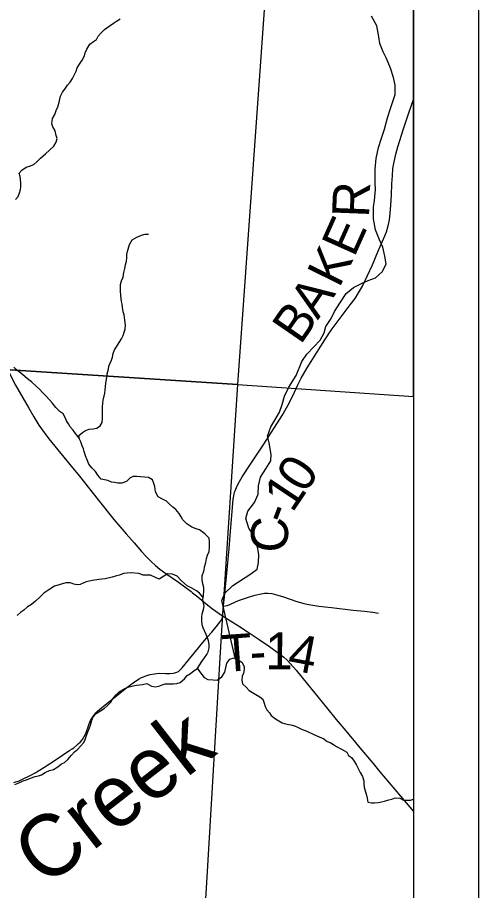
# Model space of a CAD drawing. Extents: x -8.2 to 34, y 0 to 22.
# Drawn here: x 8.292 to 9, y 18.744 to 20.084 of the extents above; entities that cross this region are included whole.
import ezdxf

# ---------------------------------------------------------------- set-up
doc = ezdxf.new("R2010")
doc.units = 0
for name, color, linetype in [('GM_X_Corporation', 7, 'Continuous'), ('GM_X_County_Road', 7, 'Continuous'), ('GM_X_County_Road_Text', 7, 'Continuous'), ('GM_X_Minor_River', 7, 'Continuous'), ('GM_X_Minor_River_Text', 7, 'Continuous'), ('GM_X_State_Route', 7, 'Continuous'), ('GM_X_Township_Road', 7, 'Continuous'), ('GM_X_Township_Road_Text', 7, 'Continuous'), ('SH_Data', 7, 'Continuous')]:
    doc.layers.add(name, color=color, linetype=linetype)

msp = doc.modelspace()

# ---------------------------------------------------------------- linework, layer by layer
at = {"layer": 'GM_X_Corporation'}
for points in [[(7.6877, 20.6096), (8.7029, 20.5419), (8.6299, 19.5206), (7.6147, 19.5864)], [(8.9, 19.5025), (8.9, 20.5285), (8.7029, 20.5419), (8.6299, 19.5206)], [(7.6147, 19.5864), (8.6299, 19.5206), (8.6049, 19.1351), (8.5816, 18.7383), (8.5636, 18.5025), (7.9912, 18.537), (7.548, 18.5656), (7.5613, 18.7777), (7.5889, 19.1864)]]:
    msp.add_lwpolyline(points, close=True, dxfattribs=at)
at = {"layer": 'GM_X_County_Road'}
for points in [[(8.6077, 19.1703), (8.6086, 19.1801), (8.6087, 19.1813), (8.61, 19.1947), (8.6135, 19.231), (8.617, 19.269), (8.619, 19.2886), (8.6214, 19.3195), (8.6222, 19.3317), (8.6235, 19.3444), (8.6248, 19.3524), (8.6256, 19.3556), (8.6263, 19.3574), (8.6285, 19.3627), (8.6309, 19.3679), (8.6371, 19.3789), (8.649, 19.3969), (8.6704, 19.429), (8.6984, 19.4731), (8.7094, 19.492), (8.7176, 19.5089), (8.7227, 19.5202), (8.7277, 19.5302), (8.737, 19.5463), (8.7518, 19.5697), (8.7641, 19.5894), (8.7736, 19.604), (8.7874, 19.6228), (8.8032, 19.6428), (8.8105, 19.6529), (8.8159, 19.6613), (8.8217, 19.6717), (8.8297, 19.6879), (8.8371, 19.7044), (8.8455, 19.7244), (8.8561, 19.7489), (8.8585, 19.7554), (8.8611, 19.7644), (8.8631, 19.7736), (8.8646, 19.7835), (8.8656, 19.7959), (8.8663, 19.8114), (8.8669, 19.8287), (8.8677, 19.841), (8.8687, 19.8522), (8.8705, 19.8627), (8.8732, 19.8746), (8.8763, 19.8859), (8.885, 19.9131), (8.8922, 19.9349), (8.8971, 19.9496), (8.9, 19.9584)], [(8.2869, 18.9093), (8.2948, 18.9123), (8.2992, 18.9141), (8.3031, 18.916), (8.3066, 18.9178), (8.3116, 18.9203), (8.3195, 18.9246), (8.3326, 18.9327), (8.35, 18.9439), (8.3729, 18.959), (8.3762, 18.9612), (8.3786, 18.9629), (8.3833, 18.9667), (8.3857, 18.9688), (8.3889, 18.9719), (8.392, 18.9757), (8.3948, 18.9801), (8.3966, 18.9838), (8.3982, 18.988), (8.4006, 18.9948), (8.4023, 18.9994), (8.4046, 19.0046), (8.4063, 19.0077), (8.4082, 19.0106), (8.4128, 19.0166), (8.4153, 19.0192), (8.418, 19.0217), (8.4268, 19.0288), (8.4622, 19.0569), (8.472, 19.0643), (8.4791, 19.0688), (8.4828, 19.0708), (8.4855, 19.072), (8.4909, 19.074), (8.4959, 19.0752), (8.5024, 19.0764), (8.506, 19.0768), (8.5103, 19.0772), (8.5196, 19.0769), (8.5264, 19.0767), (8.5312, 19.0773), (8.534, 19.0779), (8.5368, 19.079), (8.5393, 19.0802), (8.5418, 19.0824), (8.545, 19.0856), (8.5566, 19.0995), (8.5634, 19.1079), (8.5722, 19.1187), (8.5843, 19.1336), (8.5906, 19.1406), (8.5992, 19.1509), (8.6043, 19.158), (8.606, 19.1608), (8.6068, 19.1631), (8.6071, 19.1657)], [(8.6071, 19.1657), (8.6076, 19.1694), (8.6077, 19.1703)]]:
    msp.add_lwpolyline(points, dxfattribs=at)
at = {"layer": 'GM_X_Minor_River'}
for points in [[(8.6272, 19.0985), (8.606, 19.1888), (8.6108, 19.2005), (8.6227, 19.2121), (8.6503, 19.2299), (8.6603, 19.2373), (8.6623, 19.2476), (8.6629, 19.2593), (8.6611, 19.2689), (8.6565, 19.286), (8.6476, 19.3003), (8.6429, 19.3148), (8.6461, 19.3261), (8.6562, 19.3393), (8.6617, 19.3521), (8.6623, 19.365), (8.6651, 19.3783), (8.6733, 19.3914), (8.6811, 19.4035), (8.6816, 19.413), (8.6785, 19.4312), (8.6763, 19.4412), (8.6811, 19.4559), (8.6874, 19.4661), (8.6944, 19.4781), (8.6987, 19.4898), (8.7023, 19.5027), (8.7086, 19.5166), (8.7199, 19.5347), (8.729, 19.5562), (8.7363, 19.5671), (8.7471, 19.5784), (8.7568, 19.5888), (8.763, 19.5998), (8.7658, 19.6096), (8.774, 19.622), (8.7791, 19.6329), (8.7873, 19.6457), (8.7966, 19.6604), (8.8081, 19.6697), (8.8203, 19.6756), (8.8307, 19.6804), (8.8421, 19.6844), (8.8525, 19.6941), (8.8584, 19.7061), (8.8563, 19.718), (8.8531, 19.7317), (8.8479, 19.7428), (8.8417, 19.7581), (8.839, 19.7749), (8.8389, 19.7931), (8.8402, 19.8034), (8.8416, 19.8201), (8.8413, 19.8299), (8.8411, 19.8417), (8.8413, 19.8516), (8.8431, 19.8679), (8.8464, 19.8846), (8.8511, 19.8989), (8.8559, 19.9129), (8.8604, 19.9303), (8.8647, 19.9443), (8.8687, 19.9553), (8.8719, 19.9659), (8.8721, 19.9803), (8.8697, 19.9921), (8.865, 20.0066), (8.8587, 20.0212), (8.8536, 20.0315), (8.8485, 20.0445), (8.8471, 20.0544), (8.844, 20.0716), (8.8355, 20.0862)], [(8.2891, 19.805), (8.2936, 19.8092), (8.2955, 19.8149), (8.2969, 19.8199), (8.2973, 19.8244), (8.2976, 19.8298), (8.2971, 19.8355), (8.2963, 19.84), (8.2951, 19.8453), (8.2989, 19.8499), (8.3057, 19.8542), (8.3106, 19.8561), (8.3174, 19.8584), (8.3223, 19.8631), (8.3275, 19.8684), (8.3354, 19.875), (8.3482, 19.8865), (8.3519, 19.8926), (8.353, 19.8983), (8.3518, 19.9032), (8.3502, 19.9104), (8.3464, 19.9165), (8.3452, 19.921), (8.3463, 19.929), (8.3496, 19.9355), (8.3518, 19.9416), (8.354, 19.9473), (8.3562, 19.9542), (8.3584, 19.9633), (8.3614, 19.9694), (8.3648, 19.9744), (8.3689, 19.9805), (8.373, 19.9851), (8.3767, 19.9905), (8.3793, 19.9955), (8.3823, 20.0019), (8.3841, 20.0069), (8.3886, 20.0142), (8.3916, 20.0188), (8.3953, 20.0253), (8.3961, 20.0298), (8.3986, 20.0359), (8.4035, 20.0432), (8.4091, 20.0474), (8.4137, 20.0505), (8.4159, 20.0555), (8.4208, 20.0608), (8.4257, 20.0658), (8.4328, 20.0712), (8.4396, 20.0758), (8.4445, 20.0785), (8.4501, 20.0824)], [(8.4381, 19.5628), (8.4392, 19.5681), (8.4414, 19.5738), (8.4444, 19.5784), (8.4482, 19.5853), (8.4519, 19.5907), (8.4545, 19.596), (8.4563, 19.601), (8.4574, 19.6055), (8.4581, 19.612), (8.4573, 19.6196), (8.4561, 19.6276), (8.4545, 19.6321), (8.4537, 19.6393), (8.4532, 19.6439), (8.452, 19.6484), (8.4512, 19.6575), (8.4504, 19.6644), (8.4503, 19.6693), (8.4506, 19.6743), (8.4521, 19.68), (8.4543, 19.6857), (8.4558, 19.6925), (8.4572, 19.6986), (8.4583, 19.7047), (8.4594, 19.7101), (8.4601, 19.7154), (8.4604, 19.7203), (8.4611, 19.7249), (8.4644, 19.7359), (8.4685, 19.7428), (8.4753, 19.7471), (8.4825, 19.7498), (8.4882, 19.7514), (8.4935, 19.7514)], [(8.5682, 19.0843), (8.5755, 19.0955), (8.5796, 19.1009), (8.583, 19.1059), (8.5852, 19.1104), (8.5863, 19.1165), (8.5866, 19.1215), (8.5854, 19.1272), (8.5842, 19.1317), (8.5819, 19.1366), (8.5792, 19.1423), (8.5772, 19.1468), (8.5757, 19.1518), (8.5752, 19.1582), (8.5755, 19.1636), (8.5759, 19.1685), (8.5777, 19.175), (8.5788, 19.1803), (8.578, 19.1849), (8.5768, 19.1902), (8.5779, 19.1966), (8.5782, 19.2039), (8.5781, 19.2088), (8.5765, 19.2164), (8.5757, 19.2213), (8.576, 19.227), (8.5782, 19.2339), (8.58, 19.2423), (8.5815, 19.2472), (8.5826, 19.2537), (8.584, 19.2586), (8.5863, 19.2644), (8.5873, 19.2716), (8.5872, 19.2788), (8.5864, 19.2849), (8.5799, 19.2913), (8.5719, 19.2973), (8.5665, 19.2991), (8.5601, 19.3017), (8.5524, 19.3066), (8.5463, 19.313), (8.5436, 19.3175), (8.5405, 19.3224), (8.5355, 19.3289), (8.5309, 19.3322), (8.5259, 19.3371), (8.5209, 19.3416), (8.5148, 19.3446), (8.5083, 19.3484), (8.5041, 19.3559), (8.5029, 19.3639), (8.5013, 19.37), (8.4997, 19.3745), (8.4936, 19.3779), (8.4871, 19.3786), (8.475, 19.3796), (8.47, 19.3795), (8.4651, 19.3776), (8.4599, 19.3719), (8.4527, 19.3691), (8.4462, 19.3694), (8.4413, 19.3702), (8.4367, 19.3709), (8.431, 19.3731), (8.4208, 19.3753), (8.4158, 19.3817), (8.4119, 19.387), (8.4065, 19.3926), (8.4019, 19.3983), (8.3992, 19.4051), (8.3965, 19.4112), (8.3945, 19.4176), (8.3937, 19.4221), (8.3918, 19.4267), (8.3894, 19.4324), (8.3875, 19.4369), (8.3863, 19.4422), (8.3919, 19.4468), (8.3968, 19.4499), (8.4025, 19.4523), (8.4086, 19.4527), (8.4139, 19.4535), (8.4191, 19.4574), (8.4221, 19.4623), (8.4228, 19.4688), (8.4227, 19.4809), (8.423, 19.487), (8.4233, 19.4916), (8.424, 19.4965), (8.4266, 19.5076), (8.4272, 19.5175), (8.4279, 19.5224), (8.4294, 19.5319), (8.4301, 19.5373), (8.4319, 19.5445), (8.4326, 19.5491), (8.4367, 19.5582), (8.4381, 19.5628)], [(8.3872, 19.4383), (8.3813, 19.4452), (8.3778, 19.4505), (8.3732, 19.4558), (8.3705, 19.4603), (8.3674, 19.4648), (8.3655, 19.4701), (8.3624, 19.4754), (8.3578, 19.4788), (8.3513, 19.4852), (8.3455, 19.4924), (8.3417, 19.4973), (8.3359, 19.5033), (8.3309, 19.5086), (8.3267, 19.5131), (8.3217, 19.5176), (8.3137, 19.5248), (8.3076, 19.5296), (8.2999, 19.536), (8.2926, 19.5417), (8.2865, 19.5473)], [(8.5771, 19.1938), (8.5717, 19.2), (8.5672, 19.2038), (8.5599, 19.2079), (8.553, 19.2116), (8.5481, 19.2154), (8.5435, 19.2199), (8.5373, 19.2263), (8.5305, 19.2293), (8.5232, 19.2299), (8.5168, 19.2265), (8.51, 19.2215), (8.5043, 19.2244), (8.4967, 19.2278), (8.4899, 19.2277), (8.4853, 19.2277), (8.4788, 19.2307), (8.4667, 19.2313), (8.4606, 19.2309), (8.4549, 19.2304), (8.4489, 19.2281), (8.4443, 19.2269), (8.4379, 19.225), (8.4269, 19.2222), (8.4216, 19.2218), (8.4171, 19.221), (8.4076, 19.2197), (8.4023, 19.2185), (8.3977, 19.2177), (8.3932, 19.2154), (8.3883, 19.2135), (8.3837, 19.213), (8.3788, 19.2141), (8.3738, 19.216), (8.3663, 19.2163), (8.3579, 19.2136), (8.3489, 19.2108), (8.3402, 19.2054), (8.333, 19.2004), (8.327, 19.1947), (8.3199, 19.1881), (8.3138, 19.1831), (8.3078, 19.1793), (8.3018, 19.1743), (8.2973, 19.1712), (8.292, 19.1662)], [(8.2883, 18.9062), (8.2936, 18.9086), (8.3008, 18.9121), (8.306, 18.9136), (8.3121, 18.916), (8.3193, 18.9187), (8.3246, 18.9199), (8.3291, 18.9214), (8.3348, 18.9249), (8.3416, 18.928), (8.3476, 18.9296), (8.354, 18.9335), (8.3601, 18.9381), (8.3646, 18.94), (8.3695, 18.945), (8.3751, 18.9515), (8.38, 18.9565), (8.3849, 18.9607), (8.3939, 18.9707), (8.3961, 18.9753), (8.3983, 18.9818), (8.4002, 18.9871), (8.4031, 18.9932), (8.4046, 18.9978), (8.4064, 19.005), (8.4086, 19.0104), (8.4131, 19.0157), (8.4196, 19.0196), (8.4256, 19.0231), (8.4301, 19.0273), (8.4354, 19.033), (8.438, 19.0376), (8.4436, 19.0441), (8.4485, 19.0487), (8.4534, 19.0518), (8.4579, 19.0545), (8.4636, 19.0565), (8.47, 19.0577), (8.4749, 19.0589), (8.4795, 19.0593), (8.4844, 19.0601), (8.4908, 19.0613), (8.4981, 19.0576), (8.5034, 19.0565), (8.5091, 19.0573), (8.5144, 19.0596), (8.5189, 19.0608), (8.5254, 19.0612), (8.5318, 19.0609), (8.5368, 19.0617), (8.5421, 19.0633), (8.5488, 19.0687), (8.5526, 19.074), (8.5579, 19.0767), (8.5635, 19.0817), (8.5684, 19.0844), (8.5715, 19.0799), (8.5753, 19.0754), (8.5788, 19.0705), (8.5845, 19.0679), (8.5929, 19.0672), (8.5986, 19.0669), (8.6061, 19.0719), (8.6106, 19.0788), (8.6128, 19.0883), (8.6139, 19.0928), (8.6183, 19.099), (8.6248, 19.1009), (8.6309, 19.098), (8.6366, 19.0942), (8.6401, 19.0878), (8.6405, 19.0828), (8.6394, 19.0775), (8.6372, 19.0729), (8.6365, 19.0665), (8.6377, 19.0612), (8.6431, 19.0559), (8.6477, 19.051), (8.653, 19.0476), (8.658, 19.0446), (8.6645, 19.0409), (8.6691, 19.0375), (8.6711, 19.0311), (8.6726, 19.0261), (8.675, 19.0212), (8.6792, 19.0167), (8.6819, 19.0122), (8.6884, 19.0073), (8.6933, 19.0043), (8.6987, 19.0013), (8.7059, 18.9991), (8.712, 18.998), (8.7177, 18.9965), (8.7223, 18.9947), (8.7284, 18.9913), (8.7364, 18.9884), (8.7471, 18.9831), (8.7555, 18.9798), (8.7623, 18.9764), (8.7677, 18.9727), (8.7723, 18.9708)], [(8.7723, 18.9708), (8.7772, 18.9678), (8.7818, 18.9648), (8.7898, 18.9607), (8.7978, 18.9559), (8.8002, 18.951), (8.8048, 18.948), (8.809, 18.9423), (8.8129, 18.9359), (8.8152, 18.931), (8.8183, 18.9249), (8.8221, 18.9185), (8.8237, 18.912), (8.8238, 18.9071), (8.8246, 18.9022), (8.8258, 18.8969), (8.8281, 18.89), (8.8293, 18.8855), (8.8301, 18.8794), (8.8359, 18.8783), (8.8404, 18.8784), (8.8457, 18.8788), (8.851, 18.88), (8.8556, 18.8808), (8.8624, 18.8828), (8.8669, 18.8839), (8.8722, 18.8859), (8.8794, 18.8852), (8.8848, 18.8826), (8.8897, 18.8823), (8.8958, 18.8823), (8.9, 18.8841)]]:
    msp.add_lwpolyline(points, dxfattribs=at)
at = {"layer": 'GM_X_State_Route'}
for points in [[(8.2752, 19.5469), (8.2893, 19.5198), (8.3007, 19.5002), (8.3098, 19.4841), (8.3173, 19.4708), (8.3249, 19.4585), (8.3332, 19.4468), (8.3405, 19.4375), (8.3589, 19.4148), (8.3726, 19.3981), (8.3877, 19.3798), (8.4162, 19.3436), (8.4404, 19.3134), (8.4591, 19.2914), (8.4714, 19.2774), (8.4828, 19.2643), (8.4903, 19.256), (8.4973, 19.2489), (8.5042, 19.2425), (8.5109, 19.2371), (8.5199, 19.2304), (8.5393, 19.2169), (8.5589, 19.2027), (8.5612, 19.2008)], [(8.5612, 19.2008), (8.569, 19.1946), (8.5819, 19.1839), (8.5918, 19.1762), (8.6071, 19.1657), (8.6318, 19.1499), (8.6448, 19.1414), (8.6633, 19.129), (8.6789, 19.1181), (8.693, 19.1082), (8.701, 19.102), (8.7056, 19.0979), (8.7116, 19.0918), (8.7201, 19.0819), (8.7373, 19.0607), (8.7467, 19.0491), (8.7667, 19.0245), (8.7817, 19.0063), (8.7964, 18.9886), (8.8055, 18.9776), (8.8091, 18.9733), (8.8154, 18.9657), (8.8265, 18.9523), (8.8381, 18.9385), (8.8483, 18.926), (8.8629, 18.909), (8.889, 18.8782), (8.9, 18.8652)]]:
    msp.add_lwpolyline(points, dxfattribs=at)
at = {"layer": 'GM_X_Township_Road'}
msp.add_lwpolyline([(8.6086, 19.1801), (8.6144, 19.1813), (8.6171, 19.1822), (8.6195, 19.1835), (8.6316, 19.1888), (8.6439, 19.1932), (8.6564, 19.197), (8.6661, 19.1993), (8.6716, 19.2001), (8.6766, 19.2002), (8.6827, 19.1995), (8.69, 19.1978), (8.6989, 19.1951), (8.7211, 19.1873), (8.7265, 19.1857), (8.732, 19.1843), (8.7393, 19.1829), (8.7547, 19.1804), (8.7741, 19.1782), (8.8076, 19.1742), (8.8251, 19.1725), (8.8377, 19.1711), (8.8463, 19.1697)], dxfattribs=at)
at = {"layer": 'SH_Data'}
for p, q in [((9, 21), (9, 14)), ((8.9, 20.9), (8.9, 14.1))]:
    msp.add_line(p, q, dxfattribs=at)

# ---------------------------------------------------------------- texts
at = {"layer": 'GM_X_County_Road_Text'}
for s, rotation, p in [('R', 87.7824, (8.8318, 19.7764)), ('E', 65.9004, (8.8091, 19.7147)), ('K', 63.7729, (8.786, 19.6678)), ('A', 55.585, (8.7533, 19.6189)), ('B', 55.4428, (8.7267, 19.5803)), ('0', 56.62, (8.7338, 19.3518)), ('1', 56.1988, (8.7141, 19.3224)), ('-', 69.3626, (8.7075, 19.3036)), ('C', 87.4506, (8.7063, 19.2616))]:
    msp.add_text(s, height=0.0568, rotation=rotation, dxfattribs=at).set_placement(p)
at = {"layer": 'GM_X_Minor_River_Text'}
msp.add_text('Creek', height=0.0947, rotation=37.9502, dxfattribs=at).set_placement((8.3345, 18.7468))
at = {"layer": 'GM_X_Township_Road_Text'}
for s, rotation, p in [('T', 4.0102, (8.6081, 19.079)), ('1', 359.8751, (8.6727, 19.0832)), ('4', 349.3749, (8.7049, 19.0834)), ('-', 3.2019, (8.6502, 19.0819))]:
    msp.add_text(s, height=0.0568, rotation=rotation, dxfattribs=at).set_placement(p)

doc.saveas('drawing.dxf')
